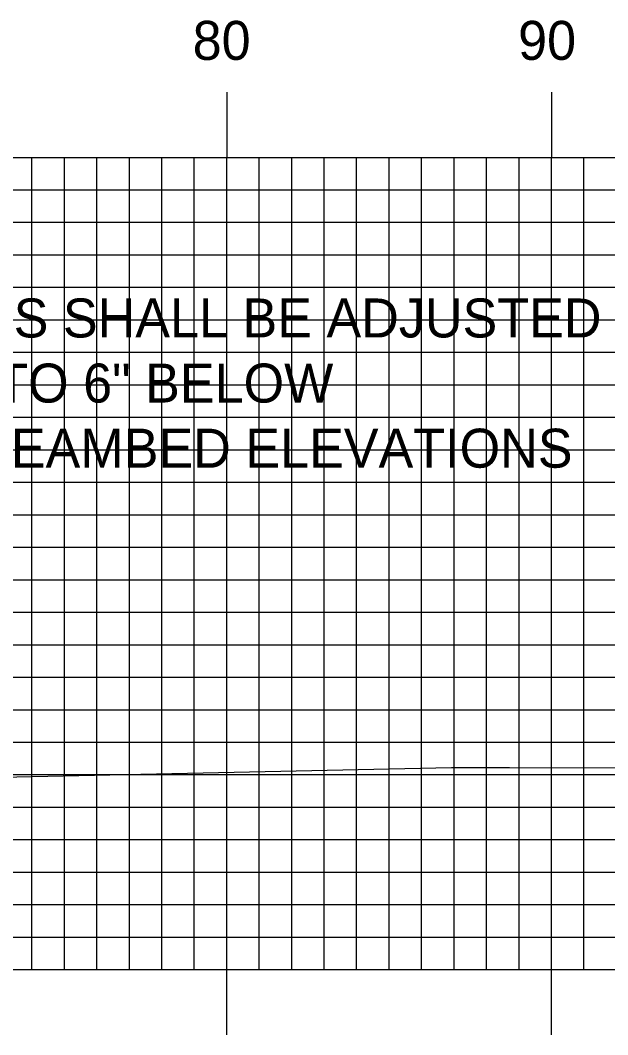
# Model space of a CAD drawing. Extents: x 1814915 to 1815259, y 442591 to 442811.
# Drawn here: x 1815154.66 to 1815172.75, y 442741.66 to 442772.88 of the extents above; entities that cross this region are included whole.
import ezdxf

# ---------------------------------------------------------------- set-up
doc = ezdxf.new("R2010")
doc.units = 0
for name, color, linetype in [('ANNOTATION', 7, 'Continuous'), ('H_V ANNOTATION', 7, 'Continuous'), ('MAJOR', 7, 'Continuous'), ('MINOR', 7, 'Continuous'), ('S_Roadway_Centerline', 7, 'Continuous')]:
    doc.layers.add(name, color=color, linetype=linetype)

msp = doc.modelspace()

# ---------------------------------------------------------------- linework, layer by layer
at = {"layer": 'MAJOR'}
for p, q in [((1815161.021, 442770.669), (1815161.021, 442768.665)), ((1815171.021, 442770.669), (1815171.021, 442768.665)), ((1814941.021, 442768.665), (1815221.021, 442768.665)), ((1814941.021, 442768.665), (1815221.021, 442768.665)), ((1815161.021, 442743.665), (1815161.021, 442768.665)), ((1815171.021, 442743.665), (1815171.021, 442768.665)), ((1814941.021, 442763.665), (1815221.021, 442763.665)), ((1814941.021, 442758.665), (1815221.021, 442758.665)), ((1814941.021, 442753.665), (1815221.021, 442753.665)), ((1814941.021, 442748.665), (1815221.021, 442748.665)), ((1814941.021, 442743.665), (1815221.021, 442743.665)), ((1814941.021, 442743.665), (1815221.021, 442743.665)), ((1815161.021, 442741.661), (1815161.021, 442743.665)), ((1815171.021, 442741.661), (1815171.021, 442743.665))]:
    msp.add_line(p, q, dxfattribs=at)
at = {"layer": 'MINOR'}
for p, q in [((1815155.021, 442743.665), (1815155.021, 442768.665)), ((1815156.021, 442743.665), (1815156.021, 442768.665)), ((1815157.021, 442743.665), (1815157.021, 442768.665)), ((1815158.021, 442743.665), (1815158.021, 442768.665)), ((1815159.021, 442743.665), (1815159.021, 442768.665)), ((1815160.021, 442743.665), (1815160.021, 442768.665)), ((1815162.021, 442743.665), (1815162.021, 442768.665)), ((1815163.021, 442743.665), (1815163.021, 442768.665)), ((1815164.021, 442743.665), (1815164.021, 442768.665)), ((1815165.021, 442743.665), (1815165.021, 442768.665)), ((1815166.021, 442743.665), (1815166.021, 442768.665)), ((1815167.021, 442743.665), (1815167.021, 442768.665)), ((1815168.021, 442743.665), (1815168.021, 442768.665)), ((1815169.021, 442743.665), (1815169.021, 442768.665)), ((1815170.021, 442743.665), (1815170.021, 442768.665)), ((1815172.021, 442743.665), (1815172.021, 442768.665)), ((1814941.021, 442767.665), (1815221.021, 442767.665)), ((1814941.021, 442766.665), (1815221.021, 442766.665)), ((1814941.021, 442765.665), (1815221.021, 442765.665)), ((1814941.021, 442764.665), (1815221.021, 442764.665)), ((1814941.021, 442762.665), (1815221.021, 442762.665)), ((1814941.021, 442761.665), (1815221.021, 442761.665)), ((1814941.021, 442760.665), (1815221.021, 442760.665)), ((1814941.021, 442759.665), (1815221.021, 442759.665)), ((1814941.021, 442757.665), (1815221.021, 442757.665)), ((1814941.021, 442756.665), (1815221.021, 442756.665)), ((1814941.021, 442755.665), (1815221.021, 442755.665)), ((1814941.021, 442754.665), (1815221.021, 442754.665)), ((1814941.021, 442752.665), (1815221.021, 442752.665)), ((1814941.021, 442751.665), (1815221.021, 442751.665)), ((1814941.021, 442750.665), (1815221.021, 442750.665)), ((1814941.021, 442749.665), (1815221.021, 442749.665)), ((1814941.021, 442747.665), (1815221.021, 442747.665)), ((1814941.021, 442746.665), (1815221.021, 442746.665)), ((1814941.021, 442745.665), (1815221.021, 442745.665)), ((1814941.021, 442744.665), (1815221.021, 442744.665))]:
    msp.add_line(p, q, dxfattribs=at)
at = {"layer": 'S_Roadway_Centerline'}
msp.add_lwpolyline([(1815126.402, 442749.71), (1815137.574, 442749.683), (1815150.597, 442749.63), (1815154.07, 442749.585), (1815167.94, 442749.887), (1815169.729, 442749.89), (1815182.088, 442749.867), (1815187.773, 442749.84), (1815188.896, 442749.837), (1815204.004, 442749.615), (1815215.497, 442749.683), (1815220.278, 442749.598), (1815221.021, 442749.604)], dxfattribs=at)

# ---------------------------------------------------------------- texts
at = {"layer": 'ANNOTATION'}
for s, p in [('NOTE: INVERTS SHALL BE ADJUSTED ', (1815143.225, 442763.121)), ('IN THE FIELD TO 6" BELOW', (1815143.225, 442761.117)), ('EXISTING STREAMBED ELEVATIONS', (1815143.225, 442759.113))]:
    msp.add_text(s, height=1.2, dxfattribs=at).set_placement(p)
at = {"layer": 'H_V ANNOTATION'}
for s, p in [('80', (1815159.971, 442771.665)), ('90', (1815169.993, 442771.665))]:
    msp.add_text(s, height=1.2, dxfattribs=at).set_placement(p)

doc.saveas('drawing.dxf')
